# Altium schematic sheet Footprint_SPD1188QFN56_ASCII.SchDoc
size A4; 项目编号: SPSZ2023-052501A; 项目名称: 三相PFC-2.2KW压机+700W风机
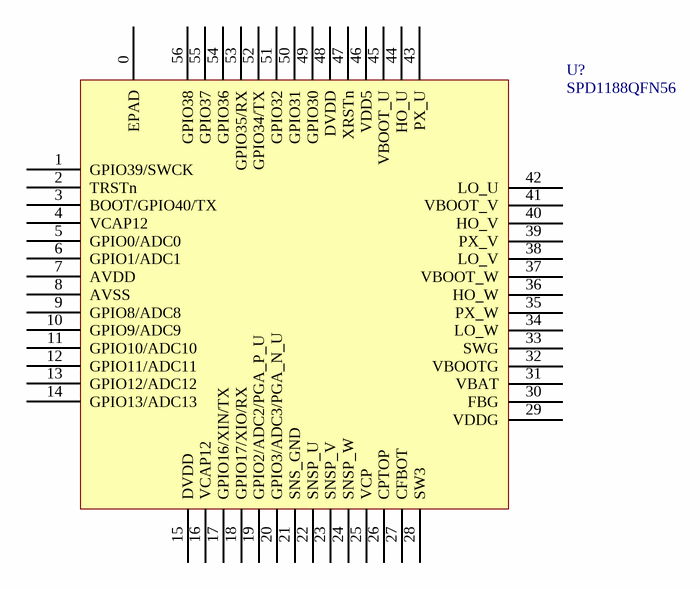
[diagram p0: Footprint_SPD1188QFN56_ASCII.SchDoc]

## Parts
U?  SPD1188QFN56  [QFN56L_20190222]

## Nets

Not connected (* = marked no-connect by the designer): U? 0(EPAD) 1(GPIO39/SWCK) 2(TRSTn) 3(BOOT/GPIO40/TX) 4(VCAP12) 5(GPIO0/ADC0) 6(GPIO1/ADC1) 7(AVDD) 8(AVSS) 9(GPIO8/ADC8) 10(GPIO9/ADC9) 11(GPIO10/ADC10) 12(GPIO11/ADC11) 13(GPIO12/ADC12) 14(GPIO13/ADC13) 15(DVDD) 16(VCAP12) 17(GPIO16/XIN/TX) 18(GPIO17/XIO/RX) 19(GPIO2/ADC2/PGA_P_U) 20(GPIO3/ADC3/PGA_N_U) 21(SNS_GND) 22(SNSP_U) 23(SNSP_V) 24(SNSP_W) 25(VCP) 26(CPTOP) 27(CFBOT) 28(SW3) 29(VDDG) 30(FBG) 31(VBAT) 32(VBOOTG) 33(SWG) 34(LO_W) 35(PX_W) 36(HO_W) 37(VBOOT_W) 38(LO_V) 39(PX_V) 40(HO_V) 41(VBOOT_V) 42(LO_U) 43(PX_U) 44(HO_U) 45(VBOOT_U) 46(VDD5) 47(XRSTn) 48(DVDD) 49(GPIO30) 50(GPIO31) 51(GPIO32) 52(GPIO34/TX) 53(GPIO35/RX) 54(GPIO36) 55(GPIO37) 56(GPIO38)

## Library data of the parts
U? = U_SPD1188_QFN56: 32-bit MCU with  Motor Pre-driver and power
